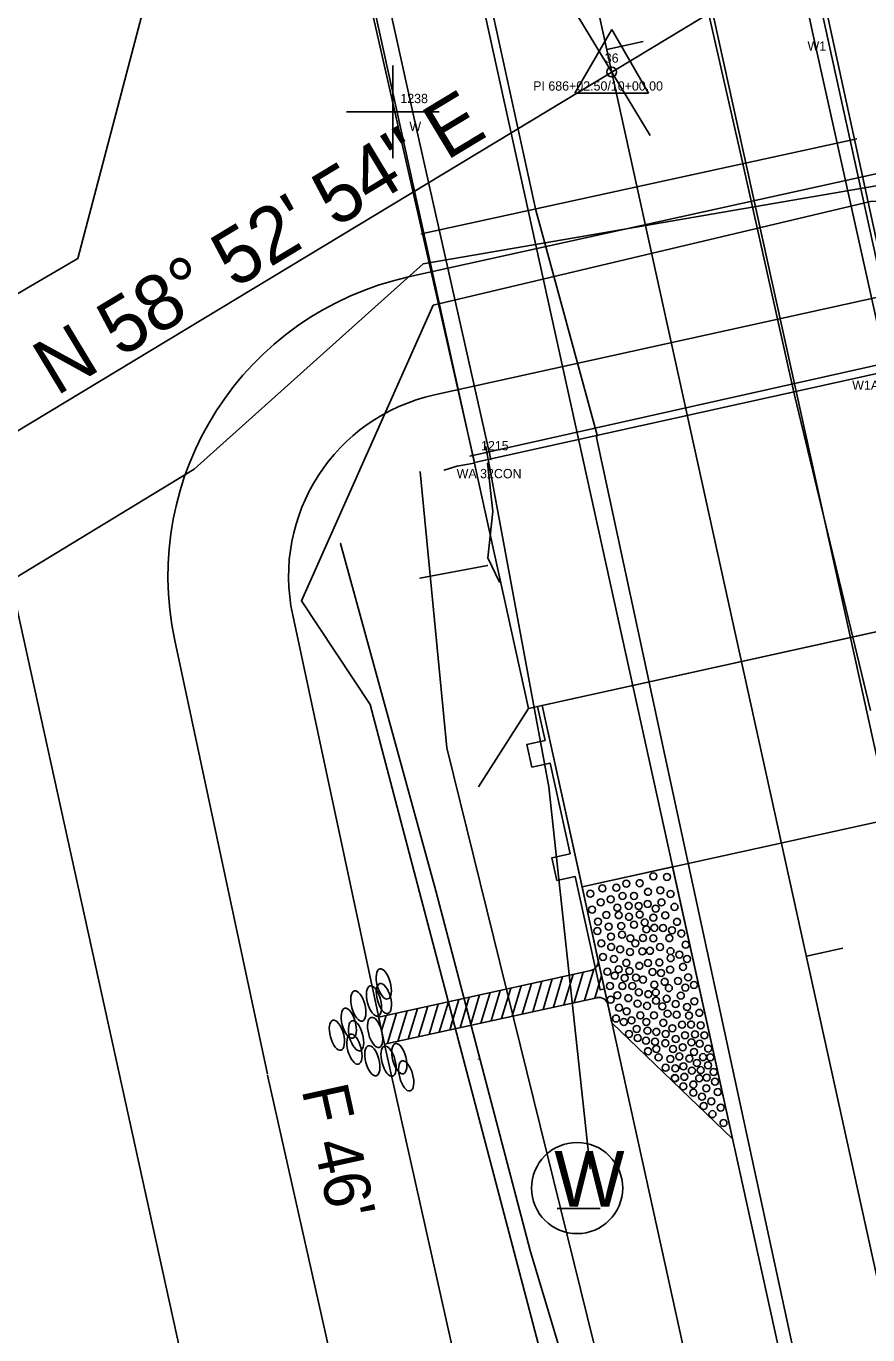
# Model space of a CAD drawing. Extents: x 2519952 to 2531965, y 848341 to 887632.
# Drawn here: x 2524206.7 to 2524297.4, y 856907.4 to 857048.4 of the extents above; entities that cross this region are included whole.
import ezdxf

# ---------------------------------------------------------------- set-up
doc = ezdxf.new("R2010")
doc.units = 0
for name, color, linetype in [('RD_EV_JW', 7, 'Continuous'), ('RD_EX_BldgApp', 7, 'Continuous'), ('RD_EX_BldgApp_txCode', 7, 'Continuous'), ('RD_EX_Bridge', 7, 'Continuous'), ('RD_EX_Conc', 7, 'Continuous'), ('RD_EX_DR_Pipe', 7, 'Continuous'), ('RD_EX_DV_Prop', 7, 'Continuous'), ('RD_EX_GuardRail', 7, 'Continuous'), ('RD_EX_H2O', 7, 'Continuous'), ('RD_EX_Misc', 7, 'Continuous'), ('RD_EX_Road', 7, 'Continuous'), ('RD_EX_RW', 7, 'Continuous'), ('RD_EX_UT', 7, 'Continuous'), ('RD_EX_VEG', 7, 'Continuous'), ('RD_HC_Cl', 7, 'Continuous'), ('RD_HC_Data', 7, 'Continuous'), ('RD_HC_Data_Tic', 7, 'Continuous'), ('RD_HC_txCode', 7, 'Continuous'), ('RD_PD_Bridge', 7, 'Continuous'), ('RD_PD_CstnLmt', 7, 'Continuous'), ('RD_PD_DR_ErosCtrl', 7, 'Continuous'), ('RD_PD_Final_TrvlWay', 7, 'Continuous'), ('RD_PD_GR', 7, 'Continuous'), ('RD_PD_PaveShd', 7, 'Continuous'), ('RD_SMD_Locator', 7, 'Continuous')]:
    doc.layers.add(name, color=color, linetype=linetype)

# ---------------------------------------------------------------- blocks, each defined once
blk = doc.blocks.new('TBC1')
at = {"layer": 'RD_PD_GR'}
blk.add_lwpolyline([(12.5, 2.5), (15, 2.5), (15, 0.49), (25, 0.49), (25, 2.5), (27.5, 2.5), (27.5, 0.49), (31.25, 0.49), (31.25, 0), (0, 0), (0, 0.49), (12.5, 0.49)], close=True, dxfattribs=at)

msp = doc.modelspace()

# ---------------------------------------------------------------- linework, layer by layer
at = {"layer": 'RD_EV_JW'}
msp.add_lwpolyline([(2524307.83, 856393.41), (2524347.51, 856441.44), (2524366.03, 856458.61), (2524362.85, 856506.49), (2524327.82, 856660.19), (2524303.01, 856757.56), (2524284.34, 856838.66), (2524260.99, 856916.53), (2524250.82, 856955.25), (2524240.58, 856992.67)], dxfattribs=at)
at = {"layer": 'RD_EX_BldgApp'}
for points in [[(2524299.52, 857011.21), (2524291.4, 857047.73), (2524283.39, 857085.27)], [(2524256.76, 857001.69), (2524248.36, 857039.08), (2524240.29, 857075.67)]]:
    msp.add_lwpolyline(points, dxfattribs=at)
at = {"layer": 'RD_EX_Bridge'}
for points in [[(2524254.99, 857001.37), (2524301.28, 857011.6), (2524285.15, 857085.66), (2524238.23, 857075.21), (2524254.99, 857001.37)], [(2524254.98, 857001.31), (2524253.1, 857000.98), (2524251.75, 857000.57)]]:
    msp.add_lwpolyline(points, dxfattribs=at)
at = {"layer": 'RD_EX_Conc'}
msp.add_lwpolyline([(2524257.69, 856988.48), (2524256.44, 856991.13), (2524256.96, 856996.11), (2524256.41, 857001.31)], dxfattribs=at)
at = {"layer": 'RD_EX_DR_Pipe'}
msp.add_line((2524256.4, 856990.29), (2524249.12, 856988.91), dxfattribs=at)
at = {"layer": 'RD_EX_DV_Prop'}
msp.add_line((2524163.74, 857176.23), (2524228.26, 856883.25), dxfattribs=at)
at = {"layer": 'RD_EX_GuardRail'}
msp.add_lwpolyline([(2524267.46, 856925.35), (2524262.99, 856966.46), (2524256.23, 857003.07)], dxfattribs=at)
at = {"layer": 'RD_EX_H2O'}
for points in [[(2524062.9, 856690.11), (2524078.2, 856780.75), (2524107.67, 856825.52), (2524103.84, 856852.05), (2524066.66, 856879.2), (2524081.02, 856897.89), (2524113.14, 856921.45), (2524159.25, 856960.82), (2524224.8, 857000.66), (2524249.46, 857022.77), (2524305.55, 857032.43), (2524305.55, 857032.43), (2524325.32, 857034.6), (2524370.33, 857078.7)], [(2524221.83, 857059.69), (2524212.27, 857023.34), (2524144.98, 856984.03), (2524094.95, 856945.79), (2524039.03, 856896.4), (2524040.7, 856866.19), (2523970.09, 856835.53)], [(2524272.81, 856864.89), (2524243.76, 856975.33), (2524236.35, 856986.49), (2524250.55, 857018.32), (2524297.65, 857029.48), (2524307.91, 857029.77)]]:
    msp.add_lwpolyline(points, dxfattribs=at)
at = {"layer": 'RD_EX_Misc'}
for p, q in [((2524246.21, 857034.14), (2524246.21, 857044.14)), ((2524241.21, 857039.14), (2524251.21, 857039.14)), ((2524296.17, 857036.24), (2524249.29, 857025.99)), ((2524254.51, 857002.08), (2524301.43, 857012.55))]:
    msp.add_line(p, q, dxfattribs=at)
at = {"layer": 'RD_EX_Road'}
for p, q in [((2524283.87, 857033.71), (2524278.38, 857057.92)), ((2524261.6, 857028.54), (2524256.26, 857052.98)), ((2524289.4, 857008.96), (2524283.87, 857033.71)), ((2524268.22, 857004.31), (2524261.6, 857028.54)), ((2524289.46, 857008.65), (2524289.4, 857008.96)), ((2524297.66, 856974.69), (2524289.46, 857008.65)), ((2524268.13, 857004.08), (2524268.22, 857004.31)), ((2524275.55, 856969.68), (2524268.13, 857004.08)), ((2524297.08, 856870.07), (2524275.55, 856969.68))]:
    msp.add_line(p, q, dxfattribs=at)
at = {"layer": 'RD_EX_RW'}
msp.add_line((2524163.74, 857176.23), (2524228.26, 856883.25), dxfattribs=at)
at = {"layer": 'RD_EX_UT'}
msp.add_line((2524263.92, 856921.04), (2524268.55, 856921.04), dxfattribs=at)
msp.add_circle((2524266.05, 856923.25), 4.91, dxfattribs=at)
at = {"layer": 'RD_EX_VEG'}
msp.add_lwpolyline([(2524280.31, 856341.99), (2524372.33, 856422.74), (2524324.66, 856676.58), (2524252.03, 856970.65), (2524249.14, 857000.39)], dxfattribs=at)
at = {"layer": 'RD_HC_Cl'}
for p, q in [((2524121.25, 857717.97), (2524677.84, 855190.33)), ((2524152.13, 856972.4), (2524317.26, 857072.09))]:
    msp.add_line(p, q, dxfattribs=at)
at = {"layer": 'RD_HC_Data'}
for p, q in [((2524265.81, 857041.14), (2524269.79, 857048.02)), ((2524269.79, 857048.02), (2524273.75, 857041.14)), ((2524265.81, 857041.14), (2524273.75, 857041.14))]:
    msp.add_line(p, q, dxfattribs=at)
msp.add_circle((2524269.78, 857043.43), 0.529, dxfattribs=at)
at = {"layer": 'RD_HC_Data_Tic'}
for p, q in [((2524269.78, 857043.43), (2524265.64, 857050.27)), ((2524269.25, 857045.87), (2524273.15, 857046.73)), ((2524269.78, 857043.43), (2524273.91, 857036.58)), ((2524290.75, 856948.21), (2524294.66, 856949.07))]:
    msp.add_line(p, q, dxfattribs=at)
at = {"layer": 'RD_PD_Bridge'}
for p, q in [((2524260.81, 856974.9), (2524306.71, 856985.01)), ((2524260.81, 856974.9), (2524255.43, 856966.47)), ((2524262.28, 856975.22), (2524266.58, 856955.69)), ((2524309.55, 856965.15), (2524266.58, 856955.69))]:
    msp.add_line(p, q, dxfattribs=at)
for points in [[(2524306.71, 856985.01), (2524278.76, 857111.96)], [(2524232.86, 857101.86), (2524260.81, 856974.9)], [(2524260.81, 856974.9), (2524306.71, 856985.01)]]:
    msp.add_lwpolyline(points, dxfattribs=at)
at = {"layer": 'RD_PD_CstnLmt'}
for p, q in [((2524235.42, 856984.95), (2524245.41, 856938.23)), ((2524245.41, 856938.23), (2524267.26, 856840.64))]:
    msp.add_line(p, q, dxfattribs=at)
msp.add_lwpolyline([(2524250.68, 857008.67), (2524301.22, 857019.8)], dxfattribs=at)
msp.add_arc((2524254.98, 856989.13), 20, 102.4185, 192.0677, dxfattribs=at)
at = {"layer": 'RD_PD_DR_ErosCtrl'}
for p, q in [((2524222.71, 856982.23), (2524232.7, 856935.51)), ((2524232.72, 856935.39), (2524254.57, 856837.8))]:
    msp.add_line(p, q, dxfattribs=at)
msp.add_lwpolyline([(2524247.88, 857021.36), (2524298.42, 857032.49)], dxfattribs=at)
msp.add_arc((2524254.98, 856989.13), 33, 102.4185, 192.0677, dxfattribs=at)
at = {"layer": 'RD_PD_Final_TrvlWay'}
for p, q in [((2524221.83, 857317.02), (2524496.02, 856071.85)), ((2524198.39, 857311.86), (2524472.58, 856066.69))]:
    msp.add_line(p, q, dxfattribs=at)
at = {"layer": 'RD_PD_GR'}
msp.add_line((2524376.52, 856456.4), (2524269, 856944.7), dxfattribs=at)
at = {"layer": 'RD_PD_PaveShd'}
for p, q in [((2524276.34, 856957.84), (2524266.58, 856955.69)), ((2524276.34, 856957.84), (2524282.8, 856928.54)), ((2524266.58, 856955.69), (2524268.51, 856946.9)), ((2524244.67, 856941.66), (2524267.54, 856946.68)), ((2524263.37, 856945.77), (2524262.39, 856942.48)), ((2524264.49, 856946.02), (2524263.5, 856942.73)), ((2524264.49, 856946.02), (2524263.5, 856942.73)), ((2524265.61, 856946.26), (2524264.62, 856942.97)), ((2524265.61, 856946.26), (2524264.62, 856942.97)), ((2524266.72, 856946.51), (2524265.74, 856943.22)), ((2524266.72, 856946.51), (2524265.74, 856943.22)), ((2524267.86, 856946.82), (2524266.86, 856943.46)), ((2524268.69, 856946.1), (2524267.97, 856943.71)), ((2524268.51, 856946.9), (2524269.16, 856943.97)), ((2524257.78, 856944.54), (2524256.8, 856941.25)), ((2524257.78, 856944.54), (2524256.8, 856941.25)), ((2524258.9, 856944.79), (2524257.92, 856941.5)), ((2524258.9, 856944.79), (2524257.92, 856941.5)), ((2524260.02, 856945.03), (2524259.04, 856941.75)), ((2524260.02, 856945.03), (2524259.04, 856941.75)), ((2524261.14, 856945.28), (2524260.15, 856941.99)), ((2524261.14, 856945.28), (2524260.15, 856941.99)), ((2524262.25, 856945.52), (2524261.27, 856942.24)), ((2524262.25, 856945.52), (2524261.27, 856942.24)), ((2524268.18, 856943.75), (2524245.3, 856938.73)), ((2524251.08, 856943.07), (2524250.1, 856939.78)), ((2524251.08, 856943.07), (2524250.1, 856939.78)), ((2524252.2, 856943.32), (2524251.21, 856940.03)), ((2524252.2, 856943.32), (2524251.21, 856940.03)), ((2524253.32, 856943.56), (2524252.33, 856940.27)), ((2524253.32, 856943.56), (2524252.45, 856940.68)), ((2524254.43, 856943.81), (2524253.45, 856940.52)), ((2524254.43, 856943.81), (2524253.45, 856940.52)), ((2524255.55, 856944.05), (2524254.57, 856940.76)), ((2524255.55, 856944.05), (2524254.57, 856940.76)), ((2524256.67, 856944.3), (2524255.68, 856941.01)), ((2524256.67, 856944.3), (2524255.68, 856941.01)), ((2524269.16, 856943.97), (2524269.8, 856941.04)), ((2524245.3, 856938.73), (2524244.67, 856941.66)), ((2524245.49, 856941.84), (2524244.99, 856940.17)), ((2524246.61, 856942.09), (2524245.63, 856938.8)), ((2524246.61, 856942.09), (2524245.75, 856939.21)), ((2524247.73, 856942.33), (2524246.75, 856939.05)), ((2524247.73, 856942.33), (2524246.75, 856939.05)), ((2524248.85, 856942.58), (2524247.86, 856939.29)), ((2524248.85, 856942.58), (2524247.86, 856939.29)), ((2524249.96, 856942.82), (2524248.98, 856939.54)), ((2524249.96, 856942.82), (2524248.98, 856939.54)), ((2524282.8, 856928.54), (2524269.8, 856941.04))]:
    msp.add_line(p, q, dxfattribs=at)
for centre in [(2524274.26, 856956.82), (2524274.26, 856956.82), (2524275.73, 856956.75), (2524275.73, 856956.75), (2524268.78, 856955.52), (2524268.78, 856955.52), (2524270.27, 856955.59), (2524270.27, 856955.59), (2524271.34, 856956.04), (2524271.34, 856956.04), (2524272.78, 856956.08), (2524272.78, 856956.08), (2524275.01, 856955.31), (2524275.01, 856955.31), (2524267.47, 856954.94), (2524267.47, 856954.94), (2524267.47, 856954.94), (2524268.6, 856954.02), (2524268.6, 856954.02), (2524269.67, 856954.34), (2524269.67, 856954.34), (2524270.94, 856954.71), (2524270.94, 856954.71), (2524272.18, 856954.71), (2524272.18, 856954.71), (2524273.64, 856953.84), (2524273.64, 856953.84), (2524273.7, 856955.15), (2524273.7, 856955.15), (2524275.14, 856954.01), (2524275.14, 856954.01), (2524276.11, 856954.92), (2524276.11, 856954.92), (2524267.66, 856953.23), (2524267.66, 856953.23), (2524269.21, 856952.66), (2524269.21, 856952.66), (2524270.38, 856953.44), (2524270.38, 856953.44), (2524270.53, 856952.64), (2524270.53, 856952.64), (2524271.61, 856953.64), (2524271.61, 856953.64), (2524271.63, 856952.46), (2524271.63, 856952.46), (2524272.69, 856953.63), (2524272.69, 856953.63), (2524272.78, 856952.71), (2524272.78, 856952.71), (2524274.51, 856953.34), (2524274.51, 856953.34), (2524275.54, 856952.61), (2524275.54, 856952.61), (2524276.54, 856953.53), (2524276.54, 856953.53), (2524268.29, 856951.94), (2524268.29, 856951.94), (2524269.46, 856951.41), (2524269.46, 856951.41), (2524270.8, 856951.46), (2524270.8, 856951.46), (2524272.19, 856951.61), (2524272.19, 856951.61), (2524273.34, 856951.85), (2524273.51, 856951.11), (2524273.51, 856951.11), (2524274.27, 856952.37), (2524274.27, 856952.37), (2524274.38, 856951.27), (2524274.38, 856951.27), (2524275.31, 856951.25), (2524275.31, 856951.25), (2524276.8, 856951.92), (2524276.8, 856951.92), (2524268.24, 856950.93), (2524268.24, 856950.93), (2524269.69, 856950.33), (2524269.69, 856950.33), (2524270.89, 856950.53), (2524270.89, 856950.53), (2524271.79, 856950.15), (2524271.79, 856950.15), (2524272.31, 856949.61), (2524272.31, 856949.61), (2524273.14, 856950.17), (2524273.14, 856950.17), (2524274.25, 856950.14), (2524274.25, 856950.14), (2524275.99, 856950.16), (2524275.99, 856950.16), (2524276.27, 856951.01), (2524276.27, 856951.01), (2524277.28, 856950.66), (2524277.28, 856950.66), (2524268.65, 856949.6), (2524268.65, 856949.6), (2524269.72, 856949.22), (2524269.72, 856949.22), (2524270.69, 856948.95), (2524270.69, 856948.95), (2524271.74, 856948.66), (2524271.74, 856948.66), (2524273.07, 856948.74), (2524273.07, 856948.74), (2524273.89, 856948.8), (2524273.89, 856948.8), (2524274.98, 856949.2), (2524274.98, 856949.2), (2524276.11, 856948.76), (2524276.11, 856948.76), (2524277.07, 856948.39), (2524277.07, 856948.39), (2524277.74, 856949.45), (2524277.74, 856949.45), (2524268.83, 856948.14), (2524268.83, 856948.14), (2524270.01, 856947.92), (2524270.01, 856947.92), (2524270.52, 856946.8), (2524270.52, 856946.8), (2524271.35, 856947.5), (2524271.35, 856947.5), (2524272.76, 856947.18), (2524272.76, 856947.18), (2524273.68, 856947.48), (2524273.68, 856947.48), (2524274.92, 856947.54), (2524274.92, 856947.54), (2524276.13, 856948.01), (2524276.13, 856948.01), (2524277.47, 856947.07), (2524277.47, 856947.07), (2524277.89, 856947.93), (2524269.31, 856946.55), (2524269.31, 856946.55), (2524270.11, 856946.13), (2524270.11, 856946.13), (2524271.17, 856945.87), (2524271.17, 856945.87), (2524271.69, 856946.63), (2524271.69, 856946.63), (2524272.39, 856945.92), (2524272.39, 856945.92), (2524273.15, 856945.7), (2524273.15, 856945.7), (2524274.17, 856946.51), (2524274.17, 856946.51), (2524275.09, 856946.42), (2524275.09, 856946.42), (2524275.47, 856945.46), (2524275.47, 856945.46), (2524276.07, 856946.77), (2524276.07, 856946.77), (2524276.91, 856945.56), (2524276.91, 856945.56), (2524278.01, 856945.93), (2524278.01, 856945.93), (2524269.59, 856945.01), (2524269.59, 856945.01), (2524270.39, 856944.01), (2524270.39, 856944.01), (2524270.93, 856945), (2524270.93, 856945), (2524272.01, 856945.01), (2524272.01, 856945.01), (2524272.7, 856944.34), (2524272.7, 856944.34), (2524273.73, 856944.13), (2524273.73, 856944.13), (2524274.37, 856945.15), (2524274.37, 856945.15), (2524274.53, 856944.31), (2524274.53, 856944.31), (2524275.93, 856944.78), (2524275.93, 856944.78), (2524277.22, 856943.98), (2524277.22, 856943.98), (2524277.71, 856944.84), (2524277.71, 856944.84), (2524278.64, 856945.12), (2524278.64, 856945.12), (2524269.66, 856943.54), (2524269.66, 856943.54), (2524270.57, 856942.67), (2524270.57, 856942.67), (2524271.58, 856943.7), (2524271.58, 856943.7), (2524272.56, 856943.12), (2524272.56, 856943.12), (2524273.58, 856942.87), (2524273.58, 856942.87), (2524274.56, 856943.43), (2524274.56, 856943.43), (2524275.24, 856942.82), (2524275.24, 856942.82), (2524275.69, 856943.63), (2524275.69, 856943.63), (2524276.66, 856943.06), (2524276.66, 856943.06), (2524277.89, 856942.75), (2524277.89, 856942.75), (2524278.69, 856943.37), (2524278.69, 856943.37), (2524270.24, 856941.51), (2524270.24, 856941.51), (2524270.24, 856941.51), (2524271.38, 856942.29), (2524271.38, 856942.29), (2524271.91, 856941.3), (2524271.91, 856941.3), (2524272.86, 856941.84), (2524272.86, 856941.84), (2524274.33, 856941.84), (2524274.33, 856941.84), (2524275.79, 856942.03), (2524275.79, 856942.03), (2524276.77, 856941.92), (2524276.77, 856941.92), (2524278.09, 856941.83), (2524278.09, 856941.83), (2524279.21, 856942.12), (2524279.21, 856942.12), (2524271.08, 856941.14), (2524271.08, 856941.14), (2524271.64, 856939.85), (2524271.64, 856939.85), (2524272.47, 856940.39), (2524272.47, 856940.39), (2524273.5, 856941.14), (2524273.5, 856941.14), (2524273.63, 856940.19), (2524273.63, 856940.19), (2524274.58, 856940.07), (2524274.58, 856940.07), (2524275.33, 856941.04), (2524275.33, 856941.04), (2524275.59, 856939.85), (2524275.59, 856939.85), (2524276.31, 856940.46), (2524276.31, 856940.46), (2524277.36, 856940.84), (2524277.36, 856940.84), (2524278.33, 856940.86), (2524278.33, 856940.86), (2524278.74, 856939.8), (2524278.74, 856939.8), (2524279.36, 856940.77), (2524279.36, 856940.77), (2524272.58, 856939.4), (2524272.58, 856939.4), (2524273.47, 856939.12), (2524273.47, 856939.12), (2524274.45, 856939.01), (2524274.45, 856939.01), (2524275.56, 856938.85), (2524275.56, 856938.85), (2524276.68, 856939.3), (2524276.68, 856939.3), (2524277.43, 856938.41), (2524277.43, 856938.41), (2524277.66, 856939.7), (2524277.66, 856939.7), (2524278.37, 856938.94), (2524278.37, 856938.94), (2524279.25, 856938.79), (2524279.25, 856938.79), (2524279.76, 856939.69), (2524279.76, 856939.69), (2524273.69, 856937.99), (2524273.7, 856937.98), (2524274.59, 856938.23), (2524274.59, 856938.23), (2524274.82, 856937.33), (2524274.82, 856937.33), (2524276.09, 856937.16), (2524276.09, 856937.16), (2524276.39, 856938.22), (2524276.39, 856938.22), (2524277.07, 856937.42), (2524277.07, 856937.42), (2524278.15, 856937.2), (2524278.15, 856937.2), (2524278.65, 856937.91), (2524278.65, 856937.91), (2524279.61, 856937.35), (2524279.61, 856937.35), (2524280.17, 856938.27), (2524280.17, 856938.27), (2524280.4, 856937.33), (2524280.4, 856937.33), (2524275.58, 856936.21), (2524275.58, 856936.21), (2524276.62, 856936.14), (2524276.62, 856936.14), (2524277.5, 856936.36), (2524277.5, 856936.36), (2524278.41, 856935.9), (2524278.41, 856935.9), (2524278.95, 856936.72), (2524278.95, 856936.72), (2524279.37, 856935.95), (2524279.37, 856935.95), (2524280.15, 856936.48), (2524280.15, 856936.48), (2524280.75, 856935.75), (2524280.75, 856935.75), (2524276.58, 856935.09), (2524276.61, 856935.07), (2524277.49, 856934.2), (2524277.49, 856934.2), (2524277.59, 856935.23), (2524277.59, 856935.23), (2524278.58, 856934.4), (2524278.58, 856934.4), (2524279.2, 856935.07), (2524279.2, 856935.07), (2524280.01, 856935.15), (2524280.01, 856935.15), (2524280.89, 856934.71), (2524280.89, 856934.71), (2524278.58, 856933.52), (2524279.5, 856933.09), (2524279.5, 856933.09), (2524279.96, 856934), (2524279.96, 856934), (2524281.2, 856933.59), (2524281.2, 856933.59), (2524279.69, 856932.1), (2524279.69, 856932.1), (2524280.51, 856932.58), (2524280.51, 856932.58), (2524281.52, 856931.92), (2524281.52, 856931.92), (2524280.63, 856931.21), (2524280.63, 856931.21), (2524281.82, 856930.25)]:
    msp.add_circle(centre, 0.375, dxfattribs=at)
for centre, start, end in [((2524267.32, 856947.66), 282.3889, 12.4185), ((2524268.4, 856942.78), 12.4185, 102.3889)]:
    msp.add_arc(centre, 1, start, end, dxfattribs=at)
for centre in [(2524245.23, 856945.23), (2524245.23, 856945.23), (2524242.49, 856942.86), (2524242.49, 856942.86), (2524244.18, 856943.39), (2524244.18, 856943.39), (2524245.24, 856943.66), (2524245.24, 856943.66), (2524241.46, 856941), (2524241.46, 856941), (2524244.3, 856940.01), (2524244.3, 856940.01), (2524240.18, 856939.71), (2524240.18, 856939.71), (2524242.25, 856939.65), (2524242.25, 856939.65), (2524242.07, 856938.21), (2524242.07, 856938.21), (2524246.91, 856937.18), (2524243.99, 856936.96), (2524243.99, 856936.96), (2524245.74, 856936.91), (2524245.74, 856936.91), (2524247.64, 856935.33)]:
    msp.add_ellipse(centre, major_axis=(0.43, -1.62), ratio=0.429445, dxfattribs=at)
at = {"layer": 'RD_SMD_Locator'}
for centre in [(2524291.4, 857047.73), (2524269.78, 857043.43), (2524248.36, 857039.08), (2524296.17, 857036.24), (2524283.87, 857033.71), (2524261.6, 857028.54), (2524249.29, 857025.99), (2524212.27, 857023.34), (2524249.46, 857022.77), (2524250.55, 857018.32), (2524289.4, 857008.96), (2524289.46, 857008.65), (2524268.13, 857004.08), (2524268.22, 857004.31), (2524256.23, 857003.07), (2524253.1, 857000.98), (2524254.51, 857002.08), (2524254.98, 857001.31), (2524254.99, 857001.37), (2524254.99, 857001.37), (2524256.41, 857001.31), (2524256.76, 857001.69), (2524224.8, 857000.66), (2524249.14, 857000.39), (2524251.75, 857000.57), (2524256.96, 856996.11), (2524240.58, 856992.67), (2524256.44, 856991.13), (2524256.4, 856990.29), (2524249.12, 856988.91), (2524257.69, 856988.48), (2524236.35, 856986.49), (2524243.76, 856975.33), (2524252.03, 856970.65), (2524275.55, 856969.68), (2524262.99, 856966.46), (2524250.82, 856955.25), (2524255.42, 856937.13), (2524267.46, 856925.35), (2524260.99, 856916.53)]:
    msp.add_circle(centre, 0.001, dxfattribs=at)

# ---------------------------------------------------------------- block references
at = {"layer": 'RD_PD_Bridge', "rotation": 102.41848259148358}
msp.add_blockref('TBC1', (2524269, 856944.7), dxfattribs=at)

# ---------------------------------------------------------------- texts
at = {"layer": 'RD_EX_BldgApp_txCode'}
for s, p in [('W1', (2524290.87, 857045.73)), ('1238', (2524247.01, 857040.08)), ('W', (2524247.99, 857037.08)), ('W1A 32CON', (2524295.68, 857009.21)), ('1215', (2524255.7, 857002.69)), ('WA 32CON', (2524253.08, 856999.69))]:
    msp.add_text(s, height=1, dxfattribs=at).set_placement(p)
at = {"layer": 'RD_EX_UT'}
msp.add_text('W', height=6, dxfattribs=at).set_placement((2524263.59, 856921.25))
at = {"layer": 'RD_HC_Data'}
msp.add_text('N 58%%d 52\' 54" E', height=6, rotation=31.1184, dxfattribs=at).set_placement((2524209.96, 857008.48))
at = {"layer": 'RD_HC_txCode'}
for s, p in [('36', (2524269.03, 857044.43)), ('PI 686+02.50/10+00.00', (2524261.32, 857041.43))]:
    msp.add_text(s, height=1, dxfattribs=at).set_placement(p)
at = {"layer": 'RD_PD_CstnLmt'}
msp.add_text("F 46'", height=5, rotation=282.4185, dxfattribs=at).set_placement((2524236.36, 856933.85))

doc.saveas('drawing.dxf')
